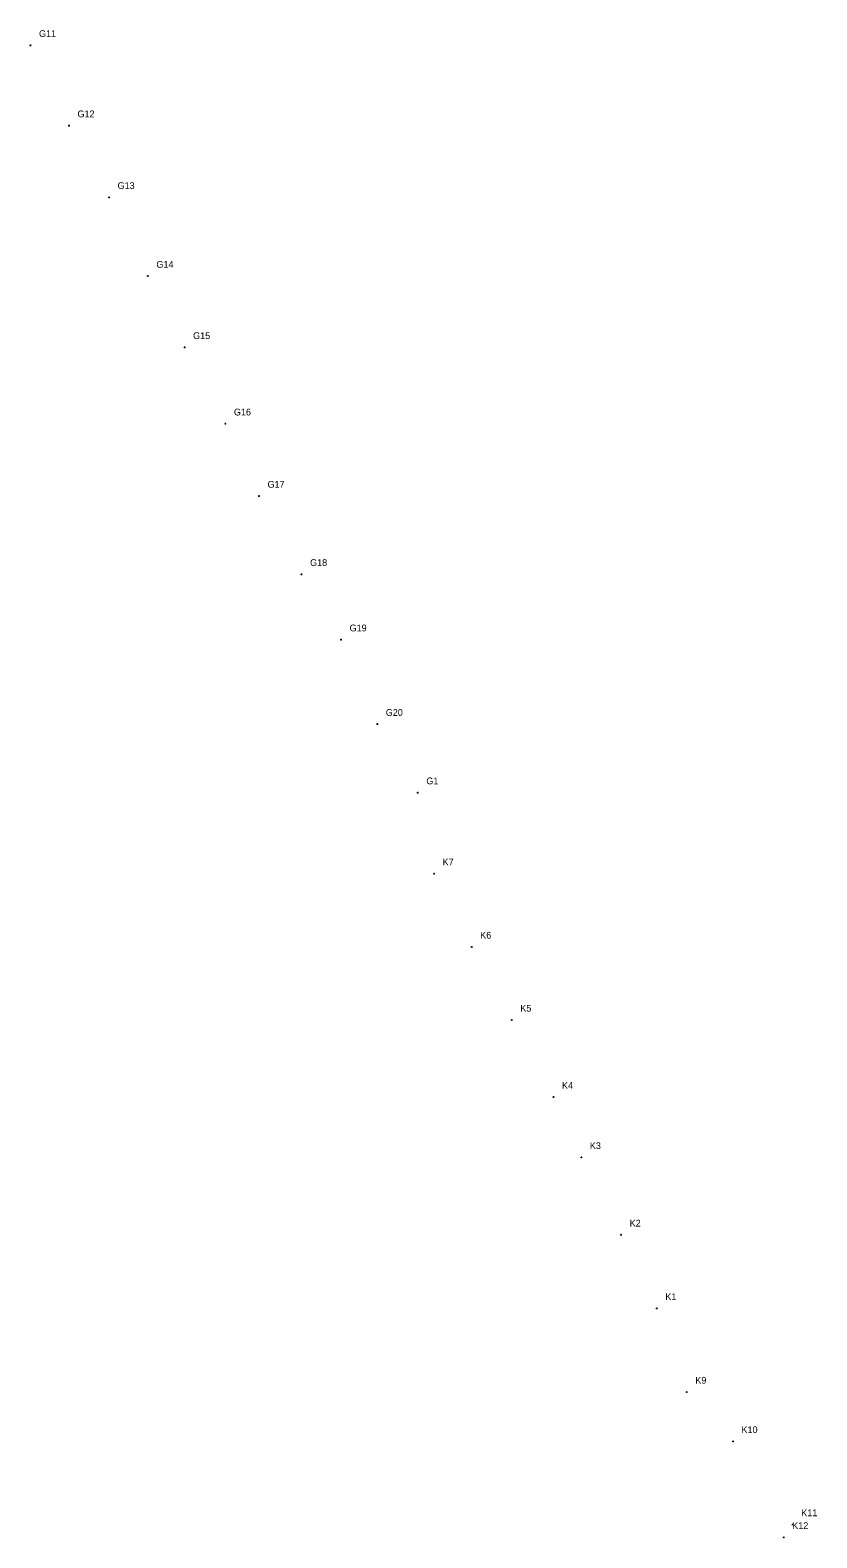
# Model space of a CAD drawing. Extents: x 1727016 to 1727482, y 654821 to 655714.
import ezdxf

# ---------------------------------------------------------------- set-up
doc = ezdxf.new("R2010")
doc.units = 0
doc.layers.add('SURVEY - DRAINAGE - Storm Sewer - Points - Locators', color=7, linetype='Continuous')
doc.layers.add('SURVEY - DRAINAGE - Storm Sewer - Points - Numbers', color=7, linetype='Continuous')

msp = doc.modelspace()

# ---------------------------------------------------------------- linework, layer by layer
at = {"layer": 'SURVEY - DRAINAGE - Storm Sewer - Points - Locators'}
for p, q in [((1727016.22, 655705.12), (1727015.72, 655705.12)), ((1727015.97, 655704.87), (1727015.97, 655705.37)), ((1727015.97, 655705.12), (1727015.97, 655705.12)), ((1727015.97, 655705.12), (1727015.97, 655705.12)), ((1727039.01, 655657.57), (1727038.51, 655657.57)), ((1727038.76, 655657.32), (1727038.76, 655657.82)), ((1727038.76, 655657.57), (1727038.76, 655657.57)), ((1727038.76, 655657.57), (1727038.76, 655657.57)), ((1727062.77, 655615.08), (1727062.27, 655615.08)), ((1727062.52, 655614.83), (1727062.52, 655615.33)), ((1727062.52, 655615.08), (1727062.52, 655615.08)), ((1727062.52, 655615.08), (1727062.52, 655615.08)), ((1727085.78, 655568.4), (1727085.28, 655568.4)), ((1727085.53, 655568.15), (1727085.53, 655568.65)), ((1727085.53, 655568.4), (1727085.53, 655568.4)), ((1727085.53, 655568.4), (1727085.53, 655568.4)), ((1727107.51, 655526.17), (1727107.01, 655526.17)), ((1727107.26, 655525.92), (1727107.26, 655526.42)), ((1727107.26, 655526.17), (1727107.26, 655526.17)), ((1727107.26, 655526.17), (1727107.26, 655526.17)), ((1727131.68, 655480.91), (1727131.18, 655480.91)), ((1727131.43, 655480.66), (1727131.43, 655481.16)), ((1727131.43, 655480.91), (1727131.43, 655480.91)), ((1727131.43, 655480.91), (1727131.43, 655480.91)), ((1727151.58, 655438.1), (1727151.08, 655438.1)), ((1727151.33, 655437.85), (1727151.33, 655438.35)), ((1727151.33, 655438.1), (1727151.33, 655438.1)), ((1727151.33, 655438.1), (1727151.33, 655438.1)), ((1727176.81, 655391.72), (1727176.31, 655391.72)), ((1727176.56, 655391.47), (1727176.56, 655391.97)), ((1727176.56, 655391.72), (1727176.56, 655391.72)), ((1727176.56, 655391.72), (1727176.56, 655391.72)), ((1727200.2, 655353.02), (1727199.7, 655353.02)), ((1727199.95, 655352.77), (1727199.95, 655353.27)), ((1727199.95, 655353.02), (1727199.95, 655353.02)), ((1727199.95, 655353.02), (1727199.95, 655353.02)), ((1727221.64, 655302.93), (1727221.14, 655302.93)), ((1727221.39, 655302.68), (1727221.39, 655303.18)), ((1727221.39, 655302.93), (1727221.39, 655302.93)), ((1727221.39, 655302.93), (1727221.39, 655302.93)), ((1727245.67, 655262.39), (1727245.17, 655262.39)), ((1727245.42, 655262.14), (1727245.42, 655262.64)), ((1727245.42, 655262.39), (1727245.42, 655262.39)), ((1727245.42, 655262.39), (1727245.42, 655262.39)), ((1727255.32, 655214.3756), (1727254.82, 655214.3756)), ((1727255.07, 655214.1256), (1727255.07, 655214.6256)), ((1727255.07, 655214.3756), (1727255.07, 655214.3756)), ((1727255.07, 655214.3756), (1727255.07, 655214.3756)), ((1727277.582, 655170.971), (1727277.082, 655170.971)), ((1727277.332, 655170.721), (1727277.332, 655171.221)), ((1727277.332, 655170.971), (1727277.332, 655170.971)), ((1727277.332, 655170.971), (1727277.332, 655170.971)), ((1727301.317, 655127.6848), (1727300.817, 655127.6848)), ((1727301.067, 655127.4348), (1727301.067, 655127.9348)), ((1727301.067, 655127.6848), (1727301.067, 655127.6848)), ((1727301.067, 655127.6848), (1727301.067, 655127.6848)), ((1727326.048, 655081.9952), (1727325.548, 655081.9952)), ((1727325.798, 655081.7452), (1727325.798, 655082.2452)), ((1727325.798, 655081.9952), (1727325.798, 655081.9952)), ((1727325.798, 655081.9952), (1727325.798, 655081.9952)), ((1727342.548, 655046.2666), (1727342.048, 655046.2666)), ((1727342.298, 655046.0166), (1727342.298, 655046.5166)), ((1727342.298, 655046.2666), (1727342.298, 655046.2666)), ((1727342.298, 655046.2666), (1727342.298, 655046.2666)), ((1727366.127, 655000.3923), (1727365.627, 655000.3923)), ((1727365.877, 655000.1423), (1727365.877, 655000.6423)), ((1727365.877, 655000.3923), (1727365.877, 655000.3923)), ((1727365.877, 655000.3923), (1727365.877, 655000.3923)), ((1727387.29, 654956.8004), (1727386.79, 654956.8004)), ((1727387.04, 654956.5504), (1727387.04, 654957.0504)), ((1727387.04, 654956.8004), (1727387.04, 654956.8004)), ((1727387.04, 654956.8004), (1727387.04, 654956.8004)), ((1727405.025, 654907.2751), (1727404.525, 654907.2751)), ((1727404.775, 654907.0251), (1727404.775, 654907.5251)), ((1727404.775, 654907.2751), (1727404.775, 654907.2751)), ((1727404.775, 654907.2751), (1727404.775, 654907.2751)), ((1727432.395, 654878.0114), (1727431.895, 654878.0114)), ((1727432.145, 654877.7614), (1727432.145, 654878.2614)), ((1727432.145, 654878.0114), (1727432.145, 654878.0114)), ((1727432.145, 654878.0114), (1727432.145, 654878.0114)), ((1727467.751, 654828.7484), (1727467.251, 654828.7484)), ((1727467.501, 654828.4984), (1727467.501, 654828.9984)), ((1727467.501, 654828.7484), (1727467.501, 654828.7484)), ((1727467.501, 654828.7484), (1727467.501, 654828.7484)), ((1727462.431, 654821.1888), (1727461.931, 654821.1888)), ((1727462.181, 654820.9388), (1727462.181, 654821.4388)), ((1727462.181, 654821.1888), (1727462.181, 654821.1888)), ((1727462.181, 654821.1888), (1727462.181, 654821.1888))]:
    msp.add_line(p, q, dxfattribs=at)

# ---------------------------------------------------------------- texts
at = {"layer": 'SURVEY - DRAINAGE - Storm Sewer - Points - Numbers'}
for s, p in [('G11', (1727020.97, 655710.12)), ('G12', (1727043.76, 655662.57)), ('G13', (1727067.52, 655620.08)), ('G14', (1727090.53, 655573.4)), ('G15', (1727112.26, 655531.17)), ('G16', (1727136.43, 655485.91)), ('G17', (1727156.33, 655443.1)), ('G18', (1727181.56, 655396.72)), ('G19', (1727204.95, 655358.02)), ('G20', (1727226.39, 655307.93)), ('G1', (1727250.42, 655267.39)), ('K7', (1727260.07, 655219.3756)), ('K6', (1727282.332, 655175.971)), ('K5', (1727306.067, 655132.6848)), ('K4', (1727330.798, 655086.9952)), ('K3', (1727347.298, 655051.2666)), ('K2', (1727370.877, 655005.3923)), ('K1', (1727392.04, 654961.8004)), ('K9', (1727409.775, 654912.2751)), ('K10', (1727437.145, 654883.0114)), ('K11', (1727472.501, 654833.7484)), ('K12', (1727467.181, 654826.1888))]:
    msp.add_text(s, height=4, dxfattribs=at).set_placement(p)

doc.saveas('drawing.dxf')
